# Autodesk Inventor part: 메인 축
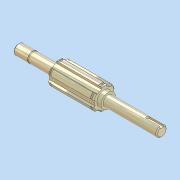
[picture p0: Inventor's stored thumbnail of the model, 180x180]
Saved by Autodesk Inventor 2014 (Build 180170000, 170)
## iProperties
Created: 2012-05
Part Number: 메인 축
Document SubType Name: 모델링
Designer: SeoGD™
Mass: 21.4461 g
Surface Area: 72.5104 cm^2
Volume: 21.4461 cm^3
Density: 1 g/cm^3
Material: 일반
Appearance: 기본값
변환 표준: STEP AP214IS
파일 이름: C:\Users\SeoGD\Desktop\?쒗뿕\硫붿씤 異?.stp
전처리기: Build: 253, Release: 2010 SP1 - Date: Wed 07/29/2009
전송 단위: 밀리미터
불확실성: 0.01
Author: SeoGD™
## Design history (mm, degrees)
sketch "스케치1"
  geometry: L1 (-69.5, 0)-(69.5, 0); L2 (69.5, 0)-(69.5, 5); L3 (69.5, 5)-(55.5, 5); L4 (55.5, 5)-(55.5, 4.8); L5 (55.5, 4.8)-(54.35, 4.8); L6 (54.35, 4.8)-(54.35, 5); L7 (54.35, 5)-(30.5, 5); L8 (30.5, 5)-(30.5, 9); L9 (30.5, 9)-(-13.5, 9); L10 (-13.5, 9)-(-13.5, 7); L11 (-13.5, 7)-(-17.5, 7); L12 (-17.5, 7)-(-17.5, 5); L13 (-17.5, 5)-(-69.5, 5); L14 (-69.5, 5)-(-69.5, 0); 2 further points
  constraints: 28 end point, 9 parallel, 4 collinear, 2 perpendicular, 1 coincident, 1 horizontal, 1 midpoint
  dimensions: "d2" = 1.15 distance between parallel lines of L6 L4; "d3" = 10 diameter of L3 L1; "d4" = 9.6 diameter of L5 L1; "d6" = 44 distance between parallel lines of L10 L8; "d7" = 4 distance between parallel lines of L12 L10; "d8" = 14 diameter of L11 L1; "d9" = 18 diameter of L9 L1; "d33" = 52 distance from line of L12.end L14; "d37" = 39 distance between parallel lines of L8 L2; "d38" = 14 distance between parallel lines of L2 L4
revolve "회전1" sketch "스케치1" stored, may be unused: angle "d10" = 90 deg
sketch "스케치2"
  geometry: L1 (2.5, 10.712)-(2.5, 8.646); L2 (-2.5, 10.712)-(-2.5, 8.646); A1 r 9 centre (0, 0) between (2.5, 8.646) and (-2.5, 8.646) reference; A2 r 11 centre (0, 0) between (2.5, 10.712) and (-2.5, 10.712); 1 further point
  constraints: 4 end point, 4 point on circle, 2 parallel, 1 centre point, 1 coincident, 1 vertical
  dimensions: "d11" = 22 diameter of A2; "d12" = 5 distance between parallel lines of L1 L2
extrude "돌출1" join sketch "스케치2" stored distance "d13" = 10; taper "d14" = 0 deg
chamfer "모따기1" distance "d15" = 1; stored, may be unused: second distance "d16" = 2, angle "d17" = 45 deg
node "작업 평면1"
node "작업 평면2"
sketch "스케치3"
  geometry: L1 (2.5, 10.712)-(2.5, 10.198); L2 (-2.5, 10.712)-(-2.5, 10.198); A1 r 11 centre (0, 0) between (2.5, 10.712) and (-2.5, 10.712) reference; A2 r 10.5 centre (0, 0) between (2.5, 10.198) and (-2.5, 10.198); 1 further point
  constraints: 4 end point, 2 point on circle, 1 centre point, 1 coincident, 1 parallel, 1 vertical
  dimensions: "d19" = 21 diameter of A2
extrude "돌출2" cut sketch "스케치3" distance "d20" = 1.35; taper "d21" = 0 deg
node "작업 평면3"
sketch "스케치4"
  geometry: L1 (-26, -5)-(-26, 5) reference; L2 (-26, 1.5)-(-12.5, 1.5); L3 (-12.5, -1.5)-(-26, -1.5); A1 r 1.5 centre (-12.5, 0) between (-12.5, -1.5) and (-12.5, 1.5); 2 further points
  constraints: 4 end point, 2 perpendicular, 2 point on circle, 2 point on line, 2 tangent, 1 centre point, 1 horizontal alignment, 1 midpoint
  dimensions: "d25" = 3 distance between parallel lines of L3 L2; "d26" = 15 dimension on A1 L1
extrude "돌출3" cut sketch "스케치4" distance "d27" = 1.8; taper "d28" = 0 deg
chamfer "모따기2" distance "d29" = 1; stored, may be unused: second distance "d30" = 2, angle "d31" = 45 deg
node "솔리드1"
node "솔리드 본체"
node "곡면 본체"
mirror "대칭1"
pattern_circular "원형 패턴1" dims "d23" = 360 deg
node "솔리드2"
other parameters: "d18" = -1.65
